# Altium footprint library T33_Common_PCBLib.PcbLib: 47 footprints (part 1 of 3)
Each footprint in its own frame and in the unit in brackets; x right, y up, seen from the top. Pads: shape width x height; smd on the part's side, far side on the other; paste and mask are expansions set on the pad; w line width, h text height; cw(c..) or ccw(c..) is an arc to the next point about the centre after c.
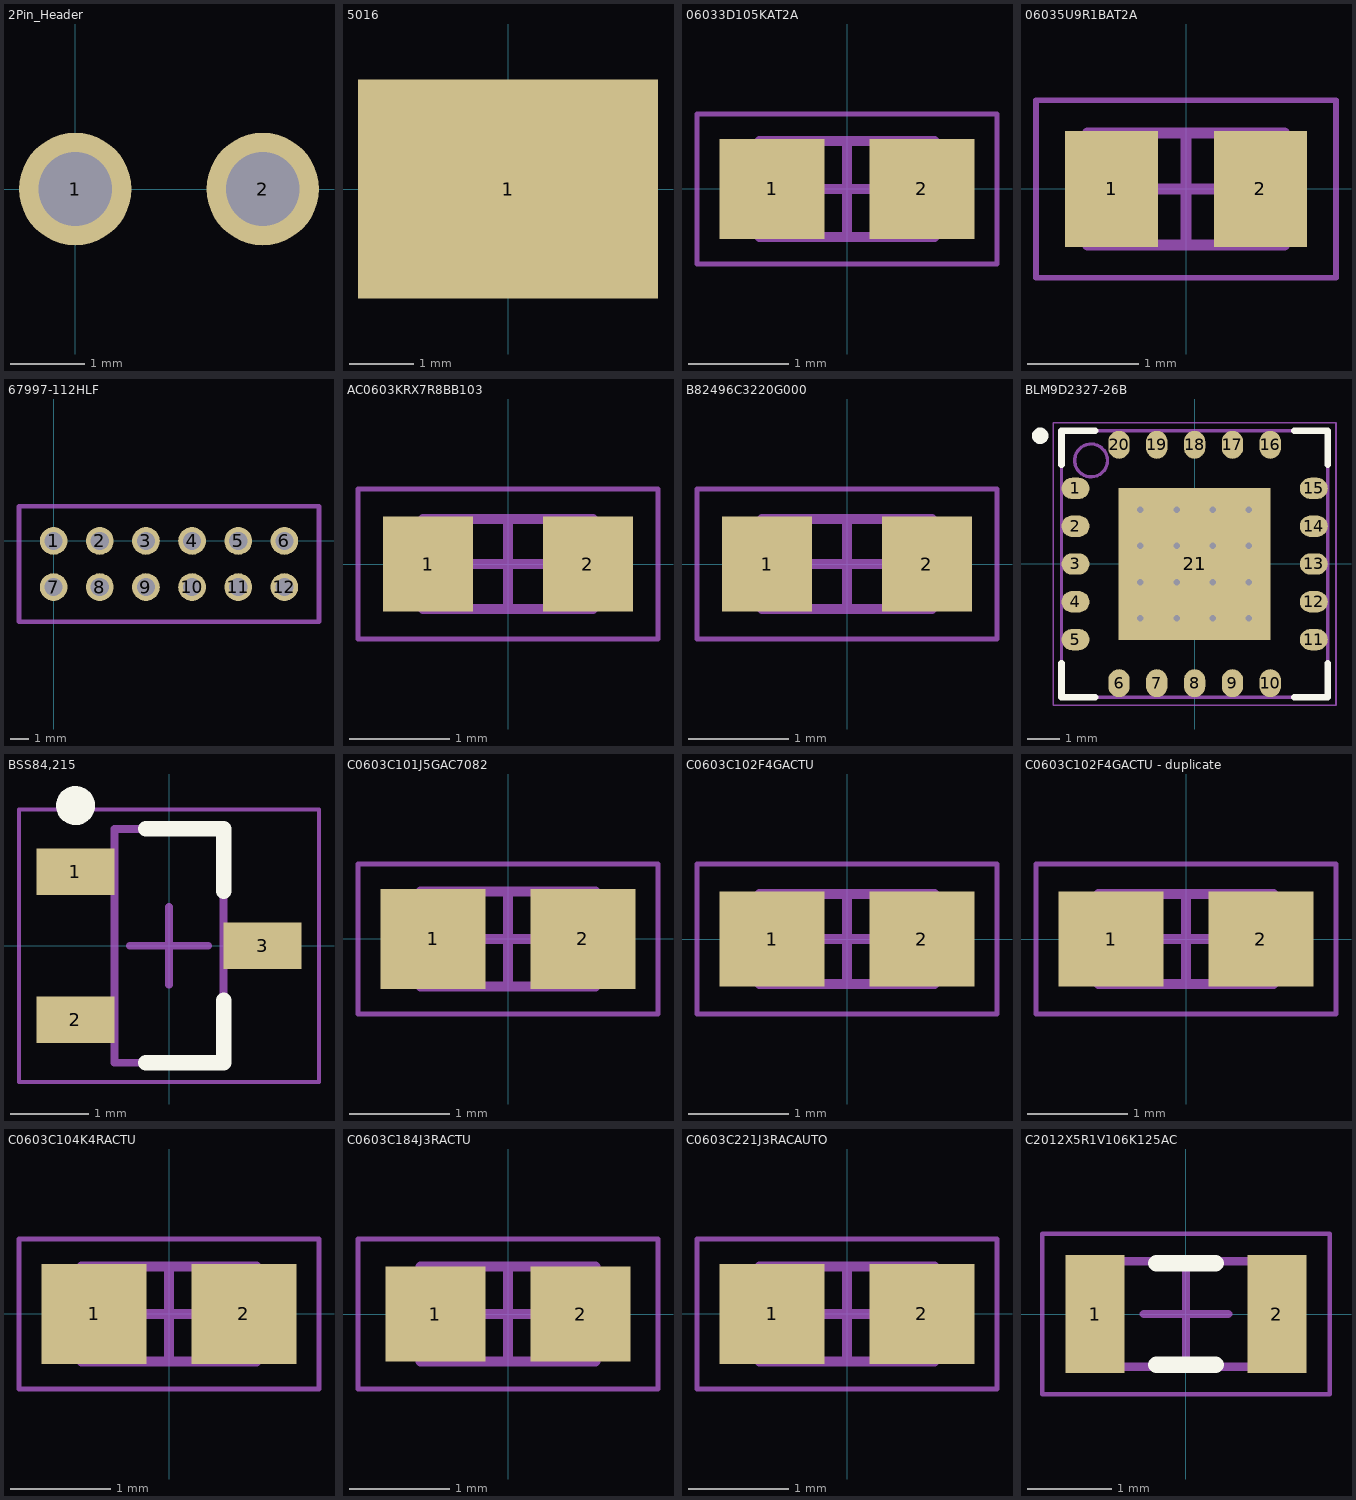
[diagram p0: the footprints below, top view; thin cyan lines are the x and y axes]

## 2Pin_Header [mil] "2Pin"
pads (2):
  round 60 hole 39.37: 1(0,0) 2(100,0)

## 5016 [mm] "Test point"
pads (1):
  rect 4.7x3.43 smd: 1(0,0)

## 06033D105KAT2A [mm] "Multilayer Ceramic Capacitors MLCC - SMD/SMT 25V 1uF X5R 0603 10%"
height 0.8
pads (2):
  rect 1.05x1 smd: 1(-0.75,0) 2(0.75,0)
Mechanical 13:
  lines w0.1: -0.875,-0.48 -0.875,0.48 0.875,0.48 0.875,-0.48 -0.875,-0.48
Mechanical 15:
  lines w0.05: -1.5,-0.75 -1.5,0.75 1.5,0.75 1.5,-0.75 -1.5,-0.75
  lines w0.1: -0.48,0 0.48,0 ; 0,-0.48 0,0.48
3D body: height 0.8, standoff 0, extent -0.525,-0.48 0.525,0.48
3D body: height 0.8, standoff 0, extent -0.875,-0.48 -0.525,0.48
3D body: height 0.8, standoff 0, extent 0.525,-0.48 0.875,0.48

## 06035U9R1BAT2A [mm] "Multilayer Ceramic Capacitors MLCC - SMD/SMT 50V 9.1pF C0G 0603 0.1pF"
height 0.91
pads (2):
  rect 0.84x1.04 smd: 1(-0.67,0) 2(0.67,0)
Mechanical 13:
  lines w0.1: -0.885,-0.505 0.885,-0.505 0.885,0.505 -0.885,0.505 -0.885,-0.505
Mechanical 15:
  lines w0.05: -1.35,-0.8 1.35,-0.8 1.35,0.8 -1.35,0.8 -1.35,-0.8
  lines w0.1: -0.5,0 0.5,0 ; 0,-0.5 0,0.5
3D body: height 0.91, standoff 0, extent 0.635,-0.505 0.885,0.505
3D body: height 0.91, standoff 0, extent -0.885,-0.505 -0.635,0.505
3D body: height 0.91, standoff 0, extent -0.635,-0.505 0.635,0.505

## 67997-112HLF [mil] "12 Pos. 2 Row Conn."
pads (12):
  round 60 hole 39.37: 1(0,0) 2(100,0) 3(200,0) 4(300,0) 5(400,0) 6(500,0) 7(0,-100) 8(100,-100) 9(200,-100) 10(300,-100) 11(400,-100) 12(500,-100)
Mechanical 1:
  lines w10: -75,-175 -75,-125 -75,75 575,75 575,0 575,-175 -75,-175

## AC0603KRX7R8BB103 [mm] "Multilayer Ceramic Capacitors MLCC - SMD/SMT 25V 0.01uF X7R 0603 10% AEC-Q200"
height 0.55
pads (2):
  rect 0.9x0.95 smd: 1(-0.8,0) 2(0.8,0)
Mechanical 13:
  lines w0.1: -0.85,-0.45 0.85,-0.45 0.85,0.45 -0.85,0.45 -0.85,-0.45
Mechanical 15:
  lines w0.05: -1.5,-0.75 1.5,-0.75 1.5,0.75 -1.5,0.75 -1.5,-0.75
  lines w0.1: -0.45,0 0.45,0 ; 0,-0.45 0,0.45
3D body: height 0.55, standoff 0, extent 0.6,-0.45 0.85,0.45
3D body: height 0.55, standoff 0, extent -0.85,-0.45 -0.6,0.45
3D body: height 0.55, standoff 0, extent -0.6,-0.45 0.6,0.45

## B82496C3220G000 [mm] "Fixed Inductors SMT-INDUCTOR 0603 22nH 2%"
height 0.94
pads (2):
  rect 0.9x0.95 smd: 1(-0.8,0) 2(0.8,0)
Mechanical 13:
  lines w0.1: -0.85,-0.45 -0.85,0.45 0.85,0.45 0.85,-0.45 -0.85,-0.45
Mechanical 15:
  lines w0.05: -1.5,-0.75 -1.5,0.75 1.5,0.75 1.5,-0.75 -1.5,-0.75
  lines w0.1: -0.45,0 0.45,0 ; 0,-0.45 0,0.45
3D body: height 0.94, standoff 0, extent -0.6,-0.45 0.6,0.45
3D body: height 0.94, standoff 0, extent -0.85,-0.45 -0.6,0.45
3D body: height 0.94, standoff 0, extent 0.6,-0.45 0.85,0.45

## BLM9D2327-26B [mm] "LDMOS 2-stage integrated Doherty MMIC"
height 2.2
pads (21):
  oval 0.85x0.65 smd: 1(-3.625,2.3) 2(-3.625,1.15) 3(-3.625,0) 4(-3.625,-1.15) 5(-3.625,-2.3) 11(3.625,-2.3) 12(3.625,-1.15) 13(3.625,0) 14(3.625,1.15) 15(3.625,2.3)
  oval 0.65x0.85 smd: 6(-2.3,-3.625) 7(-1.15,-3.625) 8(0,-3.625) 9(1.15,-3.625) 10(2.3,-3.625) 16(2.3,3.625) 17(1.15,3.625) 18(0,3.625) 19(-1.15,3.625) 20(-2.3,3.625)
  rect 4.62x4.62 smd: 21(0,0)
via 1.65,-1.65 diameter 0.5 hole 0.2
via 0.55,-1.65 diameter 0.5 hole 0.2
via -0.55,-1.65 diameter 0.5 hole 0.2
via -1.65,-1.65 diameter 0.5 hole 0.2
via 1.65,-0.55 diameter 0.5 hole 0.2
via 0.55,-0.55 diameter 0.5 hole 0.2
via -0.55,-0.55 diameter 0.5 hole 0.2
via -1.65,-0.55 diameter 0.5 hole 0.2
via 1.65,0.55 diameter 0.5 hole 0.2
via 0.55,0.55 diameter 0.5 hole 0.2
via -0.55,0.55 diameter 0.5 hole 0.2
via -1.65,0.55 diameter 0.5 hole 0.2
via 1.65,1.65 diameter 0.5 hole 0.2
via 0.55,1.65 diameter 0.5 hole 0.2
via -0.55,1.65 diameter 0.5 hole 0.2
via -1.65,1.65 diameter 0.5 hole 0.2
Top Overlay:
  circle w0.25: c-4.7,3.9 r0.125
  lines w0.2: -4.05,-3.025 -4.05,-4.05 -3.025,-4.05 ; -4.05,3.025 -4.05,4.05 -3.025,4.05 ; 3.025,-4.05 4.05,-4.05 4.05,-3.025 ; 3.025,4.05 4.05,4.05 4.05,3.025
Mechanical 13:
  circle w0.1: c-3.15,3.15 r0.5
  lines w0.1: -4.05,-4.05 4.05,-4.05 4.05,4.05 -4.05,4.05 -4.05,-4.05
Mechanical 15:
  lines w0.05: -4.3,-4.3 4.3,-4.3 4.3,4.3 -4.3,4.3 -4.3,-4.3
  lines w0.1: -0.5,0 0.5,0 ; 0,-0.5 0,0.5
3D body: height 2.2, standoff 0.05, extent -4.05,-4.05 4.05,4.05

## BSS84,215 [mm] "MOSFET P-CH DMOS 50V 130MA"
height 1.1
pads (3):
  rect 1x0.6 smd: 1(-1.2,0.95) 2(-1.2,-0.95) 3(1.2,0)
Top Overlay:
  circle w0.25: c-1.2,1.8 r0.125
  lines w0.2: -0.3,-1.5 0.7,-1.5 0.7,-0.7 ; -0.3,1.5 0.7,1.5 0.7,0.7
Mechanical 13:
  lines w0.1: -0.7,-1.5 -0.7,1.5 0.7,1.5 0.7,-1.5 -0.7,-1.5
Mechanical 15:
  lines w0.05: -1.925,-1.75 -1.925,1.75 1.925,1.75 1.925,-1.75 -1.925,-1.75
  lines w0.1: -0.5,0 0.5,0 ; 0,-0.5 0,0.5
3D body: height 1.1, standoff 0.05, extent -0.7,-1.5 0.7,1.5

## C0603C101J5GAC7082 [mm] "MLCC - SMD/SMT 50V 100pF 0603 C0G 0.05"
height 0.8
pads (2):
  rect 1.05x1 smd: 1(-0.75,0) 2(0.75,0)
Mechanical 13:
  lines w0.1: -0.875,-0.475 0.875,-0.475 0.875,0.475 -0.875,0.475 -0.875,-0.475
Mechanical 15:
  lines w0.05: -1.5,-0.75 1.5,-0.75 1.5,0.75 -1.5,0.75 -1.5,-0.75
  lines w0.1: -0.475,0 0.475,0 ; 0,-0.475 0,0.475
3D body: height 0.8, standoff 0, extent 0.525,-0.475 0.875,0.475
3D body: height 0.8, standoff 0, extent -0.875,-0.475 -0.525,0.475
3D body: height 0.8, standoff 0, extent -0.525,-0.475 0.525,0.475

## C0603C102F4GACTU [mm] "MLCC - SMD/SMT 16V 1000pF 0603 C0G 0.01"
height 0.94
pads (2):
  rect 1.05x0.95 smd: 1(-0.75,0) 2(0.75,0)
Mechanical 13:
  lines w0.1: -0.875,-0.45 -0.875,0.45 0.875,0.45 0.875,-0.45 -0.875,-0.45
Mechanical 15:
  lines w0.05: -1.5,-0.75 -1.5,0.75 1.5,0.75 1.5,-0.75 -1.5,-0.75
  lines w0.1: -0.45,0 0.45,0 ; 0,-0.45 0,0.45
3D body: height 0.94, standoff 0, extent -0.525,-0.45 0.525,0.45
3D body: height 0.94, standoff 0, extent -0.875,-0.45 -0.525,0.45
3D body: height 0.94, standoff 0, extent 0.525,-0.45 0.875,0.45

## C0603C102F4GACTU - duplicate [mm] "MLCC - SMD/SMT 16V 1000pF 0603 C0G 0.01"
height 0.94
pads (2):
  rect 1.05x0.95 smd: 1(-0.75,0) 2(0.75,0)
Mechanical 13:
  lines w0.1: -0.875,-0.45 -0.875,0.45 0.875,0.45 0.875,-0.45 -0.875,-0.45
Mechanical 15:
  lines w0.05: -1.5,-0.75 -1.5,0.75 1.5,0.75 1.5,-0.75 -1.5,-0.75
  lines w0.1: -0.45,0 0.45,0 ; 0,-0.45 0,0.45
3D body: height 0.94, standoff 0, extent -0.525,-0.45 0.525,0.45
3D body: height 0.94, standoff 0, extent -0.875,-0.45 -0.525,0.45
3D body: height 0.94, standoff 0, extent 0.525,-0.45 0.875,0.45

## C0603C104K4RACTU [mm] "MLCC - SMD/SMT 16V 0.1uF X7R 0603 10%"
height 0.8
pads (2):
  rect 1.05x1 smd: 1(-0.75,0) 2(0.75,0)
Mechanical 13:
  lines w0.1: -0.875,-0.475 -0.875,0.475 0.875,0.475 0.875,-0.475 -0.875,-0.475
Mechanical 15:
  lines w0.05: -1.5,-0.75 -1.5,0.75 1.5,0.75 1.5,-0.75 -1.5,-0.75
  lines w0.1: -0.475,0 0.475,0 ; 0,-0.475 0,0.475
3D body: height 0.8, standoff 0, extent -0.525,-0.475 0.525,0.475
3D body: height 0.8, standoff 0, extent -0.875,-0.475 -0.525,0.475
3D body: height 0.8, standoff 0, extent 0.525,-0.475 0.875,0.475

## C0603C184J3RACTU [mm] "Multilayer Ceramic Capacitors MLCC - SMD/SMT 25V 0.18uF X7R 0603 5%"
height 0.8
pads (2):
  rect 1x0.95 smd: 1(-0.725,0) 2(0.725,0)
Mechanical 13:
  lines w0.1: -0.875,-0.475 0.875,-0.475 0.875,0.475 -0.875,0.475 -0.875,-0.475
Mechanical 15:
  lines w0.05: -1.5,-0.75 1.5,-0.75 1.5,0.75 -1.5,0.75 -1.5,-0.75
  lines w0.1: -0.475,0 0.475,0 ; 0,-0.475 0,0.475
3D body: height 0.8, standoff 0, extent 0.525,-0.475 0.875,0.475
3D body: height 0.8, standoff 0, extent -0.875,-0.475 -0.525,0.475
3D body: height 0.8, standoff 0, extent -0.525,-0.475 0.525,0.475

## C0603C221J3RACAUTO [mm] "MLCC - SMD/SMT 25V 220pF X7R 0603 5% AEC-Q200"
height 0.8
pads (2):
  rect 1.05x1 smd: 1(-0.75,0) 2(0.75,0)
Mechanical 13:
  lines w0.1: -0.875,-0.475 0.875,-0.475 0.875,0.475 -0.875,0.475 -0.875,-0.475
Mechanical 15:
  lines w0.05: -1.5,-0.75 1.5,-0.75 1.5,0.75 -1.5,0.75 -1.5,-0.75
  lines w0.1: -0.475,0 0.475,0 ; 0,-0.475 0,0.475
3D body: height 0.8, standoff 0, extent 0.525,-0.475 0.875,0.475
3D body: height 0.8, standoff 0, extent -0.875,-0.475 -0.525,0.475
3D body: height 0.8, standoff 0, extent -0.525,-0.475 0.525,0.475

## C2012X5R1V106K125AC [mm] "Multilayer Ceramic Capacitors MLCC - SMD/SMT 0805 35V 10uF X5R 10% T: 1.25mm"
height 1.25
pads (2):
  rect 0.7x1.4 smd: 1(-1.075,0) 2(1.075,0)
Top Overlay:
  lines w0.2: -0.35,-0.6 0.35,-0.6 ; -0.35,0.6 0.35,0.6
Mechanical 13:
  lines w0.1: -1,-0.625 1,-0.625 1,0.625 -1,0.625 -1,-0.625
Mechanical 15:
  lines w0.05: -1.7,-0.95 1.7,-0.95 1.7,0.95 -1.7,0.95 -1.7,-0.95
  lines w0.1: -0.5,0 0.5,0 ; 0,-0.5 0,0.5
3D body: height 1.25, standoff 0, extent 0.8,-0.625 1,0.625
3D body: height 1.25, standoff 0, extent -1,-0.625 -0.8,0.625
3D body: height 1.25, standoff 0, extent -0.8,-0.625 0.8,0.625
